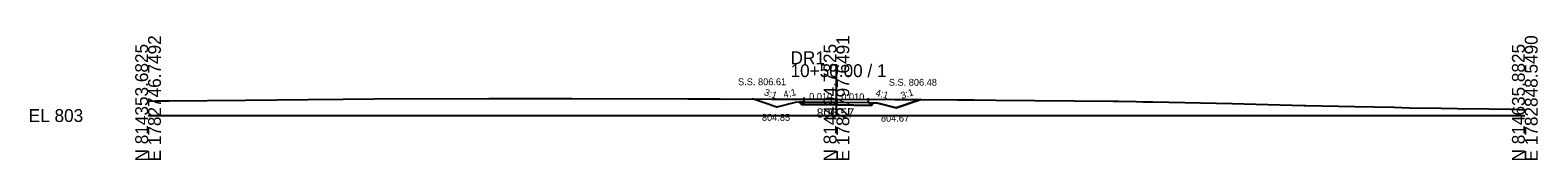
# Model space of a CAD drawing. Extents: x -26 to 303, y -10 to 2017.
# Drawn here: x -25.7 to 302.8, y 990.3 to 1017.3 of the extents above; entities that cross this region are included whole.
import ezdxf

# ---------------------------------------------------------------- set-up
doc = ezdxf.new("R2010")
doc.units = 0
for name, color, linetype in [('Exist Cross Section Cell', 7, 'Continuous'), ('Exist XS Center Line Elevation Label', 7, 'Continuous'), ('Exist XS Ground Line', 7, 'Continuous'), ('Prop XS Ditch Slope Text', 7, 'Continuous'), ('Prop XS Ditch Standard Text', 7, 'Continuous'), ('Prop XS Dump Level', 7, 'Continuous'), ('Prop XS Earthwork Shape', 7, 'Continuous'), ('Prop XS EOT Tick Mark', 7, 'Continuous'), ('Prop XS Finish Grade', 7, 'Continuous'), ('Prop XS Finish Grade Earthwork', 7, 'Continuous'), ('Prop XS Finish Grade Pavement', 7, 'Continuous'), ('Prop XS Pvmt Edge Slope', 7, 'Continuous'), ('Prop XS SE Text', 7, 'Continuous'), ('Prop XS Side Slope Text', 7, 'Continuous'), ('Prop XS SS Elevation Text', 7, 'Continuous'), ('Prop XS Subgrade Earthwork', 7, 'Continuous')]:
    doc.layers.add(name, color=color, linetype=linetype)

msp = doc.modelspace()

# ---------------------------------------------------------------- linework, layer by layer
at = {"layer": 'Exist Cross Section Cell'}
for p, q in [((150, 1000), (150, 1011.18)), ((0, 1000), (150, 1000)), ((150, 1000), (300, 1000))]:
    msp.add_line(p, q, dxfattribs=at)
at = {"layer": 'Exist XS Ground Line'}
for p, q in [((0, 1003.16), (1.63, 1003.18)), ((1.63, 1003.18), (4.57, 1003.21)), ((4.57, 1003.21), (21.2, 1003.38)), ((21.2, 1003.38), (34.87, 1003.5)), ((34.87, 1003.5), (42.51, 1003.56)), ((42.51, 1003.56), (49.28, 1003.63)), ((49.28, 1003.63), (74.22, 1003.69)), ((74.22, 1003.69), (78.26, 1003.7)), ((78.26, 1003.7), (91.34, 1003.73)), ((91.34, 1003.73), (92.29, 1003.73)), ((92.29, 1003.73), (117.65, 1003.67)), ((117.65, 1003.67), (124.66, 1003.63)), ((124.66, 1003.63), (135.9, 1003.6)), ((135.9, 1003.6), (146.83, 1003.58)), ((146.83, 1003.58), (150, 1003.57)), ((150, 1003.57), (162.64, 1003.52)), ((162.64, 1003.52), (176.29, 1003.42)), ((176.29, 1003.42), (179.91, 1003.41)), ((179.91, 1003.41), (184.76, 1003.38)), ((184.76, 1003.38), (210.32, 1003.13)), ((210.32, 1003.13), (211.44, 1003.12)), ((211.44, 1003.12), (215.3, 1003.03)), ((215.3, 1003.03), (216.8, 1003.01)), ((216.8, 1003.01), (218.93, 1002.98)), ((218.93, 1002.98), (236.3, 1002.63)), ((236.3, 1002.63), (241.44, 1002.49)), ((241.44, 1002.49), (251.92, 1002.22)), ((251.92, 1002.22), (252.31, 1002.21)), ((252.31, 1002.21), (262.94, 1001.96)), ((262.94, 1001.96), (271.55, 1001.8)), ((271.55, 1001.8), (274.88, 1001.7)), ((274.88, 1001.7), (281.74, 1001.64)), ((281.74, 1001.64), (285.3, 1001.55)), ((285.3, 1001.55), (292.25, 1001.46)), ((292.25, 1001.46), (297.07, 1001.37)), ((297.07, 1001.37), (300, 1001.27))]:
    msp.add_line(p, q, dxfattribs=at)
at = {"layer": 'Prop XS Dump Level'}
for p, q in [((143, 1002.95), (150, 1002.88)), ((150, 1002.88), (157, 1002.81))]:
    msp.add_line(p, q, dxfattribs=at)
at = {"layer": 'Prop XS Earthwork Shape'}
msp.add_lwpolyline([(131.72, 1003.61), (135.9, 1003.6), (146.83, 1003.58), (150, 1003.57), (162.64, 1003.52), (168.42, 1003.48), (163, 1001.67), (159, 1002.67), (158.1, 1002.74), (157.59, 1002.22), (149.99, 1002.3), (142.42, 1002.38), (141.9, 1002.9), (141, 1002.85), (137, 1001.85)], close=True, dxfattribs=at)
at = {"layer": 'Prop XS EOT Tick Mark'}
for p, q in [((143, 1002.95), (143, 1003.95)), ((157, 1002.81), (157, 1003.81))]:
    msp.add_line(p, q, dxfattribs=at)
at = {"layer": 'Prop XS Finish Grade'}
for p, q in [((143, 1002.95), (141.9, 1002.9)), ((157, 1002.81), (158.1, 1002.74))]:
    msp.add_line(p, q, dxfattribs=at)
at = {"layer": 'Prop XS Finish Grade Earthwork'}
for p, q in [((137, 1001.85), (131.72, 1003.61)), ((141, 1002.85), (137, 1001.85)), ((141.9, 1002.9), (141, 1002.85)), ((158.1, 1002.74), (159, 1002.67)), ((159, 1002.67), (163, 1001.67)), ((163, 1001.67), (168.42, 1003.48))]:
    msp.add_line(p, q, dxfattribs=at)
at = {"layer": 'Prop XS Finish Grade Pavement'}
for p, q in [((143, 1002.95), (150, 1002.88)), ((150, 1002.88), (157, 1002.81))]:
    msp.add_line(p, q, dxfattribs=at)
at = {"layer": 'Prop XS Pvmt Edge Slope'}
for p, q in [((143, 1002.95), (142.42, 1002.38)), ((157, 1002.81), (157.59, 1002.22))]:
    msp.add_line(p, q, dxfattribs=at)
at = {"layer": 'Prop XS Subgrade Earthwork'}
for p, q in [((142.42, 1002.38), (141.9, 1002.9)), ((142.42, 1002.38), (149.99, 1002.3)), ((149.99, 1002.3), (157.59, 1002.22)), ((157.59, 1002.22), (158.1, 1002.74))]:
    msp.add_line(p, q, dxfattribs=at)

# ---------------------------------------------------------------- texts
at = {"layer": 'Exist Cross Section Cell'}
for s, p in [('N 814353.6825', (0, 990)), ('E 1782746.7492', (2.8, 990)), ('N 814494.7825', (150, 990)), ('E 1782797.6491', (152.8, 990)), ('N 814635.8825', (300, 990)), ('E 1782848.5490', (302.8, 990))]:
    msp.add_text(s, height=2.8, rotation=90, dxfattribs=at).set_placement(p)
for s, p in [('DR1', (140, 1011.18)), ('10+50.00 / 1', (140, 1008.38)), ('EL 803', (-26, 998.6))]:
    msp.add_text(s, height=2.8, dxfattribs=at).set_placement(p)
at = {"layer": 'Exist XS Center Line Elevation Label'}
msp.add_text('806.57', height=2, dxfattribs=at).set_placement((145.7, 999.57))
at = {"layer": 'Prop XS Ditch Slope Text'}
for rotation, p in [(14.0362, (138.64, 1003.81)), (345.9638, (158.41, 1004.31))]:
    msp.add_text('4:1', height=1.5, rotation=rotation, dxfattribs=at).set_placement(p)
at = {"layer": 'Prop XS Ditch Standard Text'}
for s, p in [('804.85', (133.77, 998.85)), ('804.67', (159.7, 998.67))]:
    msp.add_text(s, height=1.5, dxfattribs=at).set_placement(p)
at = {"layer": 'Prop XS Dump Level'}
for p in [(141, 1002.81), (159, 1002.63)]:
    msp.add_text('Case1', height=0.04, dxfattribs=at).set_placement(p)
at = {"layer": 'Prop XS SE Text'}
for p in [(144.05, 1003.44), (151.05, 1003.37)]:
    msp.add_text('0.010', height=1.5, rotation=359.4271, dxfattribs=at).set_placement(p)
at = {"layer": 'Prop XS Side Slope Text'}
for rotation, p in [(341.5651, (134.11, 1004.48)), (18.4349, (164.29, 1003.58))]:
    msp.add_text('3:1', height=1.5, rotation=rotation, dxfattribs=at).set_placement(p)
at = {"layer": 'Prop XS SS Elevation Text'}
for s, p in [('S.S. 806.61', (128.56, 1006.61)), ('S.S. 806.48', (161.41, 1006.49))]:
    msp.add_text(s, height=1.5, dxfattribs=at).set_placement(p)

doc.saveas('drawing.dxf')
